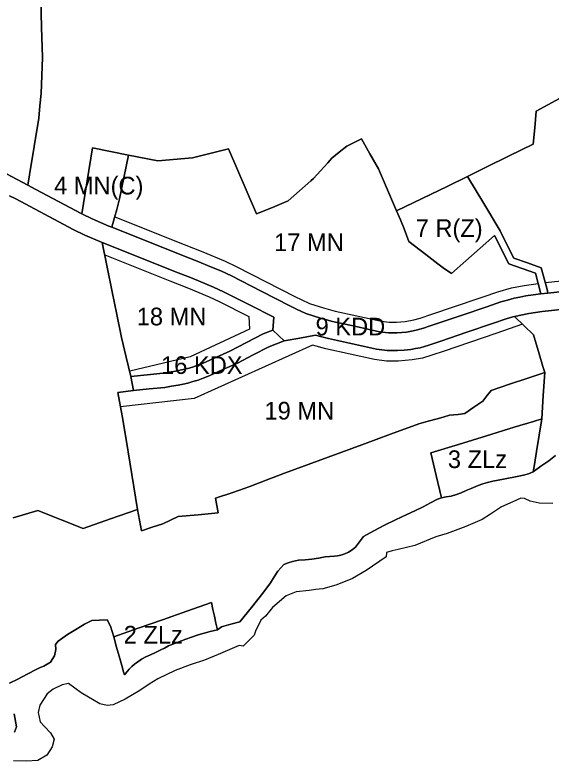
# Model space of a CAD drawing. Extents: x 7423432 to 7425824, y 5537848 to 5539677.
# Drawn here: x 7425103.3 to 7425406.3, y 5538196.8 to 5538618.6 of the extents above; entities that cross this region are included whole.
import ezdxf

# ---------------------------------------------------------------- set-up
doc = ezdxf.new("R2010")
doc.units = 0
for name, color, linetype in [('linie_rozgraniczajace', 7, 'Continuous'), ('linie_zabudowy_nieprzekraczalne', 7, 'Continuous'), ('oznaczenia_przeznaczen', 7, 'Continuous')]:
    doc.layers.add(name, color=color, linetype=linetype)

msp = doc.modelspace()

# ---------------------------------------------------------------- linework, layer by layer
at = {"layer": 'linie_rozgraniczajace'}
for points in [[(7425117.96, 5538627.54), (7425118.36, 5538611.67), (7425118.78, 5538594.47), (7425118.4, 5538584.32), (7425118.02, 5538574.17), (7425117.42, 5538567.24), (7425116.83, 5538560.3), (7425114.2, 5538544.21), (7425111.58, 5538528.12), (7425110.49, 5538522.35), (7425089.18, 5538533.67)], [(7425110.49, 5538522.35), (7425111.58, 5538528.12), (7425114.2, 5538544.21), (7425116.83, 5538560.3), (7425117.42, 5538567.24), (7425118.02, 5538574.17), (7425118.4, 5538584.32), (7425118.78, 5538594.47), (7425118.36, 5538611.67), (7425117.96, 5538627.54)], [(7425502.97, 5538619.64), (7425496.08, 5538615.71), (7425489.2, 5538611.78), (7425484.78, 5538609.38), (7425480.36, 5538606.97), (7425475.97, 5538604.58), (7425471.58, 5538602.19), (7425464.93, 5538599.13), (7425458.27, 5538596.06), (7425453.11, 5538593.1), (7425446.05, 5538589.06), (7425437.25, 5538584.6), (7425428.35, 5538580.1), (7425419.76, 5538575.77), (7425411.17, 5538571.43), (7425404.56, 5538567.83)], [(7425437.03, 5538464.83), (7425404.51, 5538461.39), (7425404.06, 5538463.37), (7425403.03, 5538467.52), (7425400.82, 5538475.69), (7425393.08, 5538478.39), (7425385.35, 5538481.09), (7425381.42, 5538488.84), (7425377.48, 5538496.59), (7425368.31, 5538511.98), (7425359.13, 5538527.36), (7425369.23, 5538532.29), (7425382.73, 5538538.88), (7425396.23, 5538545.46), (7425397.09, 5538554.85), (7425397.96, 5538564.24), (7425404.56, 5538567.83), (7425411.17, 5538571.43)], [(7425404.56, 5538567.83), (7425397.96, 5538564.24), (7425397.09, 5538554.85), (7425396.23, 5538545.46), (7425382.73, 5538538.88), (7425369.23, 5538532.29), (7425359.13, 5538527.36), (7425347.9, 5538521.89), (7425333.43, 5538514.88), (7425318.95, 5538507.87), (7425313.87, 5538519.74), (7425308.78, 5538531.62), (7425303.95, 5538540.04), (7425299.12, 5538548.47), (7425295.01, 5538546.46), (7425290.91, 5538544.46), (7425286.63, 5538541), (7425282.35, 5538537.55), (7425280.08, 5538534.91), (7425276.07, 5538530.52), (7425272.06, 5538526.13), (7425270.57, 5538524.81), (7425264.16, 5538519.15), (7425257.76, 5538513.48), (7425254.17, 5538512), (7425248.84, 5538509.8), (7425239.92, 5538506.11), (7425224.07, 5538542.82), (7425203.67, 5538537.9), (7425184.07, 5538536.07), (7425167.4, 5538539.42), (7425157.3, 5538541.44), (7425147.19, 5538543.47), (7425144.13, 5538524.8), (7425141.08, 5538506.12), (7425140.71, 5538506.31), (7425115.15, 5538519.88), (7425110.49, 5538522.35)], [(7425089.18, 5538533.67), (7425110.49, 5538522.35), (7425115.15, 5538519.88), (7425140.71, 5538506.31), (7425141.08, 5538506.12), (7425146.85, 5538503.3), (7425151.65, 5538501.27), (7425156.44, 5538499.25), (7425158.08, 5538498.59), (7425176.55, 5538491.2), (7425196.66, 5538483.15), (7425207.29, 5538479.07), (7425213.45, 5538476.46), (7425219.61, 5538473.86), (7425225.65, 5538471.04), (7425242.39, 5538462.52), (7425259.14, 5538454), (7425262.36, 5538452.27), (7425267.71, 5538449.9), (7425276.05, 5538447.21), (7425282.88, 5538445.31), (7425296.17, 5538442.42), (7425309.45, 5538439.54), (7425314.41, 5538438.87), (7425319.21, 5538438.85), (7425321.96, 5538439.11), (7425324.71, 5538439.36), (7425327.38, 5538439.85), (7425330.04, 5538440.34), (7425332.1, 5538440.91), (7425334.15, 5538441.47), (7425337.5, 5538442.6), (7425340.85, 5538443.73), (7425355.43, 5538448.66), (7425370, 5538453.59), (7425377.97, 5538456.37), (7425381.68, 5538457.4), (7425385.39, 5538458.43), (7425388.74, 5538459.1), (7425392.08, 5538459.77), (7425396.18, 5538460.36), (7425400.53, 5538460.97), (7425404.51, 5538461.39), (7425437.03, 5538464.83)], [(7425100.17, 5538516.35), (7425103.78, 5538514.59), (7425119.99, 5538505.99), (7425136.2, 5538497.38), (7425142.7, 5538494.19), (7425147.67, 5538492.1), (7425152.64, 5538490), (7425155.48, 5538476.06), (7425158.33, 5538462.13), (7425160.96, 5538449.22), (7425163.6, 5538436.3), (7425166.24, 5538425.22), (7425168.88, 5538414.14), (7425170.26, 5538406.24), (7425161.45, 5538405.16), (7425163.8, 5538391.88), (7425166.16, 5538378.59), (7425169.35, 5538358.82), (7425172.54, 5538339.09), (7425157.24, 5538333.68), (7425141.94, 5538328.32), (7425129.1, 5538333.43), (7425116.26, 5538338.55), (7425102.26, 5538334.37)], [(7425249.55, 5538447.66), (7425235.41, 5538454.86), (7425221.26, 5538462.05), (7425215.55, 5538464.72), (7425203.55, 5538469.79), (7425193.07, 5538473.82), (7425172.85, 5538481.91), (7425152.64, 5538490), (7425147.67, 5538492.1), (7425142.7, 5538494.19), (7425136.2, 5538497.38), (7425119.99, 5538505.99), (7425103.78, 5538514.59), (7425100.17, 5538516.35)], [(7425438.03, 5538454.88), (7425401.39, 5538451), (7425393.77, 5538449.91), (7425385.59, 5538448.11), (7425384.68, 5538447.85), (7425380.96, 5538446.82), (7425373.25, 5538444.13), (7425358.65, 5538439.19), (7425344.05, 5538434.26), (7425340.61, 5538433.09), (7425337.17, 5538431.93), (7425334.74, 5538431.2), (7425332.32, 5538430.47), (7425329.69, 5538429.98), (7425327.07, 5538429.5), (7425323.35, 5538429.17), (7425319.62, 5538428.84), (7425316.66, 5538428.86), (7425313.71, 5538428.87), (7425307.66, 5538429.69), (7425294.07, 5538432.65), (7425280.48, 5538435.6), (7425276.83, 5538436.62), (7425273.17, 5538437.63), (7425264.27, 5538435.96), (7425255.38, 5538434.3), (7425249.01, 5538440.45), (7425249.55, 5538447.66)], [(7425408.89, 5538369.61), (7425405.01, 5538366.49), (7425400.64, 5538363.44), (7425396.26, 5538360.39), (7425396.6, 5538362.43), (7425396.93, 5538364.48), (7425398.11, 5538371.74), (7425399.62, 5538381.03), (7425401.13, 5538390.32), (7425401.95, 5538403.43), (7425402.77, 5538416.53), (7425401.77, 5538419.88), (7425399.62, 5538427.06), (7425396.39, 5538437.82), (7425390.99, 5538442.96), (7425385.59, 5538448.11), (7425393.77, 5538449.91), (7425401.39, 5538451), (7425438.03, 5538454.88)], [(7425382.84, 5538409.81), (7425393.25, 5538413.32), (7425402.77, 5538416.53), (7425401.95, 5538403.43), (7425401.13, 5538390.32), (7425396.35, 5538388.85), (7425385.45, 5538385.49), (7425369.77, 5538380.65), (7425354.08, 5538375.81), (7425338.4, 5538370.97), (7425341.35, 5538358.27), (7425344.31, 5538345.56), (7425342.21, 5538344.95), (7425338.15, 5538342.7), (7425334.09, 5538340.46), (7425329.42, 5538338.3), (7425324.74, 5538336.15), (7425318.44, 5538333.13), (7425312.15, 5538330.1), (7425306.2, 5538326.91), (7425300.26, 5538323.73), (7425298.06, 5538320.71), (7425295.86, 5538317.7), (7425293.89, 5538316.29), (7425291.92, 5538314.89), (7425289.7, 5538314.02), (7425287.48, 5538313.16), (7425285.67, 5538312.86), (7425283.87, 5538312.56), (7425281.25, 5538312.38), (7425278.64, 5538312.19), (7425274.92, 5538311.58), (7425271.19, 5538310.96), (7425267.38, 5538310.66), (7425263.57, 5538310.35), (7425260.09, 5538309.72), (7425257.68, 5538308.87), (7425255.26, 5538308.01), (7425251.84, 5538304.2), (7425249.79, 5538300.93), (7425247.73, 5538297.66), (7425243.47, 5538291.74), (7425236.97, 5538283.62), (7425230.46, 5538275.49), (7425225.24, 5538274.13), (7425220.01, 5538272.77), (7425217.75, 5538271), (7425216.9, 5538274.85), (7425216.05, 5538278.69), (7425215.2, 5538282.53), (7425214.35, 5538286.38), (7425200.53, 5538281.54), (7425186.72, 5538276.7), (7425172.91, 5538271.86), (7425159.1, 5538267.02), (7425157.38, 5538273.1), (7425155.37, 5538276.74), (7425146.79, 5538276.22), (7425142.68, 5538274.14), (7425137.79, 5538271.28), (7425132.91, 5538268.42), (7425130.3, 5538266.53), (7425127.69, 5538264.63), (7425126.25, 5538262.68), (7425126.37, 5538259.9), (7425125.69, 5538256.36), (7425123.38, 5538252.65), (7425121.47, 5538251.6), (7425119.56, 5538250.55), (7425117.49, 5538249.63), (7425115.68, 5538248.83), (7425110.15, 5538245.9), (7425104.89, 5538243.1), (7425100.15, 5538240.76)], [(7425102.26, 5538334.37), (7425116.26, 5538338.55), (7425129.1, 5538333.43), (7425141.94, 5538328.32), (7425157.24, 5538333.68), (7425172.54, 5538339.09), (7425174.78, 5538326.99), (7425180.85, 5538328.99), (7425186.93, 5538330.98), (7425191.22, 5538333), (7425195.51, 5538335.03), (7425206.8, 5538336.06), (7425218.08, 5538337.1), (7425216.63, 5538345.39), (7425226.39, 5538348.72), (7425236.15, 5538352.04), (7425245.37, 5538355.59), (7425255.62, 5538359.55), (7425274.65, 5538366.55), (7425293.67, 5538373.55), (7425299.3, 5538375.63), (7425315.49, 5538381.59), (7425331.67, 5538387.54), (7425336.79, 5538388.93), (7425341.9, 5538390.31), (7425345.39, 5538391.3), (7425348.87, 5538392.29), (7425351.31, 5538392.55), (7425353.76, 5538392.81), (7425357.51, 5538393.35), (7425362.59, 5538396.82), (7425367.68, 5538400.28), (7425370.04, 5538403.29), (7425372.39, 5538406.29), (7425382.84, 5538409.81)], [(7425117.49, 5538249.63), (7425119.56, 5538250.55), (7425121.47, 5538251.6), (7425123.38, 5538252.65), (7425125.69, 5538256.36), (7425126.37, 5538259.9), (7425126.25, 5538262.68), (7425127.69, 5538264.63), (7425130.3, 5538266.53), (7425132.91, 5538268.42), (7425137.79, 5538271.28), (7425142.68, 5538274.14), (7425146.79, 5538276.22), (7425155.37, 5538276.74), (7425157.38, 5538273.1), (7425159.1, 5538267.02), (7425160.75, 5538261.16), (7425162.16, 5538256.18), (7425163.67, 5538250.86), (7425164.7, 5538247.21), (7425165.19, 5538245.47), (7425166.05, 5538246.54), (7425167.81, 5538248.74), (7425169.38, 5538250.19), (7425170.87, 5538251.59), (7425171.92, 5538252.34), (7425174.86, 5538254.42), (7425177.34, 5538255.68), (7425179.82, 5538256.93), (7425182.78, 5538258.27), (7425185.74, 5538259.61), (7425187.84, 5538260.71), (7425190.17, 5538261.95), (7425199.83, 5538265.69), (7425203.01, 5538266.8), (7425206.94, 5538268.17), (7425210.29, 5538269.08), (7425213.64, 5538270), (7425217.75, 5538271), (7425220.01, 5538272.77), (7425225.24, 5538274.13), (7425230.46, 5538275.49), (7425236.97, 5538283.62), (7425243.47, 5538291.74), (7425247.73, 5538297.66), (7425249.79, 5538300.93), (7425251.84, 5538304.2), (7425255.26, 5538308.01), (7425257.68, 5538308.87), (7425260.09, 5538309.72), (7425263.57, 5538310.35), (7425267.38, 5538310.66), (7425271.19, 5538310.96), (7425274.92, 5538311.58), (7425278.64, 5538312.19), (7425281.25, 5538312.38), (7425283.87, 5538312.56), (7425285.67, 5538312.86), (7425287.48, 5538313.16), (7425289.7, 5538314.02), (7425291.92, 5538314.89), (7425293.89, 5538316.29), (7425295.86, 5538317.7), (7425298.06, 5538320.71), (7425300.26, 5538323.73), (7425306.2, 5538326.91), (7425312.15, 5538330.1), (7425318.44, 5538333.13), (7425324.74, 5538336.15), (7425329.42, 5538338.3), (7425334.09, 5538340.46), (7425338.15, 5538342.7), (7425342.21, 5538344.95), (7425344.31, 5538345.56), (7425347.09, 5538346.11), (7425349.87, 5538346.65), (7425352.85, 5538347.58), (7425355.44, 5538348.39), (7425358.3, 5538349.68), (7425361.17, 5538350.97), (7425365.06, 5538352.62), (7425367.78, 5538353.5), (7425370.49, 5538354.37), (7425373.48, 5538355.01), (7425376.47, 5538355.66), (7425379.4, 5538356.21), (7425382.33, 5538356.77), (7425385.27, 5538357.32), (7425388.2, 5538357.87), (7425390.78, 5538358.52), (7425393.55, 5538359.24), (7425396.26, 5538360.39), (7425400.64, 5538363.44), (7425405.01, 5538366.49), (7425408.89, 5538369.61)], [(7425407.26, 5538342.36), (7425399.61, 5538342.57), (7425394.61, 5538343.69), (7425391.28, 5538345.22), (7425389.19, 5538345.4), (7425384.81, 5538343.44), (7425378.34, 5538340.46), (7425372.12, 5538336.44), (7425367.41, 5538333.38), (7425358.24, 5538329.36), (7425347.54, 5538325.5), (7425341.13, 5538323.66), (7425329.27, 5538318.62), (7425319.87, 5538316.49), (7425316.55, 5538315.74), (7425313.28, 5538314.69), (7425313.2, 5538312.29), (7425301.73, 5538304.56), (7425294.03, 5538300.09), (7425288.97, 5538297.97), (7425284.63, 5538296.17), (7425277.3, 5538294.27), (7425273.09, 5538293.72), (7425269.51, 5538293.19), (7425262.34, 5538292.56), (7425256.67, 5538290.14), (7425248.95, 5538283.67), (7425244.83, 5538278.72), (7425242.33, 5538276.53), (7425239.28, 5538270.16), (7425238.53, 5538268.08), (7425232.22, 5538261.74), (7425230.01, 5538262.2), (7425218.12, 5538257.07), (7425210.46, 5538253.89), (7425202.24, 5538251.13), (7425193.89, 5538247.94), (7425184.05, 5538243.3), (7425179.12, 5538240.24), (7425173.87, 5538236.71), (7425165.65, 5538231.75), (7425158.87, 5538228.68), (7425155.36, 5538228.15), (7425151.19, 5538229.26), (7425140.71, 5538235.43), (7425133.48, 5538240.71), (7425129.89, 5538239.94), (7425124.87, 5538237.43), (7425121.43, 5538234.81), (7425117.31, 5538228.46), (7425116.37, 5538224.36), (7425117.48, 5538219), (7425119.93, 5538216.34), (7425123.37, 5538212.73), (7425125.42, 5538209.19), (7425124.4, 5538204.88), (7425121.35, 5538200.07), (7425116.28, 5538197.15), (7425109.59, 5538196.81), (7425102.38, 5538196.97)], [(7425100.15, 5538240.76), (7425104.89, 5538243.1), (7425110.15, 5538245.9), (7425115.68, 5538248.83), (7425117.49, 5538249.63)], [(7425102.8, 5538223.48), (7425104.19, 5538216.25), (7425103.12, 5538213.21)], [(7425103.12, 5538213.21), (7425104.19, 5538216.25), (7425102.8, 5538223.48)]]:
    msp.add_lwpolyline(points, dxfattribs=at)
for points in [[(7425158.08, 5538498.59), (7425159.55, 5538504.03), (7425160.81, 5538508.65), (7425162.44, 5538514.65), (7425167.4, 5538539.42), (7425184.07, 5538536.07), (7425203.67, 5538537.9), (7425224.07, 5538542.82), (7425239.92, 5538506.11), (7425248.84, 5538509.8), (7425254.17, 5538512), (7425257.76, 5538513.48), (7425264.16, 5538519.15), (7425270.57, 5538524.81), (7425272.06, 5538526.13), (7425276.07, 5538530.52), (7425280.08, 5538534.91), (7425282.35, 5538537.55), (7425286.63, 5538541), (7425290.91, 5538544.46), (7425295.01, 5538546.46), (7425299.12, 5538548.47), (7425303.95, 5538540.04), (7425308.78, 5538531.62), (7425313.87, 5538519.74), (7425318.95, 5538507.87), (7425321.15, 5538502.74), (7425323.35, 5538497.61), (7425325.98, 5538490.61), (7425335.63, 5538483.14), (7425342.28, 5538477.99), (7425345.29, 5538475.66), (7425350, 5538472.47), (7425374.38, 5538493.86), (7425382.51, 5538477.85), (7425397.51, 5538472.61), (7425400.53, 5538460.97), (7425396.18, 5538460.36), (7425392.08, 5538459.77), (7425388.74, 5538459.1), (7425385.39, 5538458.43), (7425381.68, 5538457.4), (7425377.97, 5538456.37), (7425370, 5538453.59), (7425355.43, 5538448.66), (7425340.85, 5538443.73), (7425337.5, 5538442.6), (7425334.15, 5538441.47), (7425332.1, 5538440.91), (7425330.04, 5538440.34), (7425327.38, 5538439.85), (7425324.71, 5538439.36), (7425321.96, 5538439.11), (7425319.21, 5538438.85), (7425314.41, 5538438.87), (7425309.45, 5538439.54), (7425296.17, 5538442.42), (7425282.88, 5538445.31), (7425276.05, 5538447.21), (7425267.71, 5538449.9), (7425262.36, 5538452.27), (7425259.14, 5538454), (7425242.39, 5538462.52), (7425225.65, 5538471.04), (7425219.61, 5538473.86), (7425213.45, 5538476.46), (7425207.29, 5538479.07), (7425196.66, 5538483.15), (7425176.55, 5538491.2)], [(7425141.08, 5538506.12), (7425144.13, 5538524.8), (7425147.19, 5538543.47), (7425157.3, 5538541.44), (7425167.4, 5538539.42), (7425162.44, 5538514.65), (7425160.81, 5538508.65), (7425159.55, 5538504.03), (7425158.08, 5538498.59), (7425156.44, 5538499.25), (7425151.65, 5538501.27), (7425146.85, 5538503.3)], [(7425318.95, 5538507.87), (7425333.43, 5538514.88), (7425347.9, 5538521.89), (7425359.13, 5538527.36), (7425368.31, 5538511.98), (7425377.48, 5538496.59), (7425381.42, 5538488.84), (7425385.35, 5538481.09), (7425393.08, 5538478.39), (7425400.82, 5538475.69), (7425403.03, 5538467.52), (7425404.06, 5538463.37), (7425404.51, 5538461.39), (7425400.53, 5538460.97), (7425397.51, 5538472.61), (7425382.51, 5538477.85), (7425374.38, 5538493.86), (7425350, 5538472.47), (7425345.29, 5538475.66), (7425342.28, 5538477.99), (7425335.63, 5538483.14), (7425325.98, 5538490.61), (7425323.35, 5538497.61), (7425321.15, 5538502.74)], [(7425152.64, 5538490), (7425172.85, 5538481.91), (7425193.07, 5538473.82), (7425203.55, 5538469.79), (7425215.55, 5538464.72), (7425221.26, 5538462.05), (7425235.41, 5538454.86), (7425249.55, 5538447.66), (7425249.01, 5538440.45), (7425243.56, 5538438.39), (7425234.13, 5538433.49), (7425224.71, 5538428.58), (7425217.16, 5538425.17), (7425209.6, 5538421.76), (7425206.94, 5538420.73), (7425204.28, 5538419.7), (7425201.7, 5538418.99), (7425199.12, 5538418.27), (7425194.06, 5538417.2), (7425190.54, 5538416.61), (7425187.02, 5538416.01), (7425177.95, 5538415.08), (7425168.88, 5538414.14), (7425166.24, 5538425.22), (7425163.6, 5538436.3), (7425160.96, 5538449.22), (7425158.33, 5538462.13), (7425155.48, 5538476.06)], [(7425161.45, 5538405.16), (7425170.26, 5538406.24), (7425179.18, 5538407.16), (7425188.1, 5538408.08), (7425191.83, 5538408.71), (7425195.55, 5538409.34), (7425198.29, 5538409.92), (7425201.02, 5538410.5), (7425203.91, 5538411.3), (7425206.8, 5538412.1), (7425209.75, 5538413.24), (7425213.13, 5538414.57), (7425220.87, 5538418.1), (7425229.06, 5538421.83), (7425237.94, 5538426.45), (7425246.83, 5538431.07), (7425251.1, 5538432.69), (7425255.38, 5538434.3), (7425264.27, 5538435.96), (7425273.17, 5538437.63), (7425276.83, 5538436.62), (7425280.48, 5538435.6), (7425294.07, 5538432.65), (7425307.66, 5538429.69), (7425313.71, 5538428.87), (7425316.66, 5538428.86), (7425319.62, 5538428.84), (7425323.35, 5538429.17), (7425327.07, 5538429.5), (7425329.69, 5538429.98), (7425332.32, 5538430.47), (7425334.74, 5538431.2), (7425337.17, 5538431.93), (7425340.61, 5538433.09), (7425344.05, 5538434.26), (7425358.65, 5538439.19), (7425373.25, 5538444.13), (7425380.96, 5538446.82), (7425384.68, 5538447.85), (7425385.59, 5538448.11), (7425390.99, 5538442.96), (7425396.39, 5538437.82), (7425399.62, 5538427.06), (7425401.77, 5538419.88), (7425402.77, 5538416.53), (7425393.25, 5538413.32), (7425382.84, 5538409.81), (7425372.39, 5538406.29), (7425370.04, 5538403.29), (7425367.68, 5538400.28), (7425362.59, 5538396.82), (7425357.51, 5538393.35), (7425353.76, 5538392.81), (7425351.31, 5538392.55), (7425348.87, 5538392.29), (7425345.39, 5538391.3), (7425341.9, 5538390.31), (7425336.79, 5538388.93), (7425331.67, 5538387.54), (7425315.49, 5538381.59), (7425299.3, 5538375.63), (7425293.67, 5538373.55), (7425274.65, 5538366.55), (7425255.62, 5538359.55), (7425245.37, 5538355.59), (7425236.15, 5538352.04), (7425226.39, 5538348.72), (7425216.63, 5538345.39), (7425218.08, 5538337.1), (7425206.8, 5538336.06), (7425195.51, 5538335.03), (7425191.22, 5538333), (7425186.93, 5538330.98), (7425180.85, 5538328.99), (7425174.78, 5538326.99), (7425172.54, 5538339.09), (7425169.35, 5538358.82), (7425166.16, 5538378.59), (7425163.8, 5538391.88)], [(7425168.88, 5538414.14), (7425177.95, 5538415.08), (7425187.02, 5538416.01), (7425190.54, 5538416.61), (7425194.06, 5538417.2), (7425199.12, 5538418.27), (7425201.7, 5538418.99), (7425204.28, 5538419.7), (7425206.94, 5538420.73), (7425209.6, 5538421.76), (7425217.16, 5538425.17), (7425224.71, 5538428.58), (7425234.13, 5538433.49), (7425243.56, 5538438.39), (7425249.01, 5538440.45), (7425255.38, 5538434.3), (7425251.1, 5538432.69), (7425246.83, 5538431.07), (7425237.94, 5538426.45), (7425229.06, 5538421.83), (7425220.87, 5538418.1), (7425213.13, 5538414.57), (7425209.75, 5538413.24), (7425206.8, 5538412.1), (7425203.91, 5538411.3), (7425201.02, 5538410.5), (7425198.29, 5538409.92), (7425195.55, 5538409.34), (7425191.83, 5538408.71), (7425188.1, 5538408.08), (7425179.18, 5538407.16), (7425170.26, 5538406.24)], [(7425338.4, 5538370.97), (7425354.08, 5538375.81), (7425369.77, 5538380.65), (7425385.45, 5538385.49), (7425396.35, 5538388.85), (7425401.13, 5538390.32), (7425399.62, 5538381.03), (7425398.11, 5538371.74), (7425396.93, 5538364.48), (7425396.6, 5538362.43), (7425396.26, 5538360.39), (7425393.55, 5538359.24), (7425390.78, 5538358.52), (7425388.2, 5538357.87), (7425385.27, 5538357.32), (7425382.33, 5538356.77), (7425379.4, 5538356.21), (7425376.47, 5538355.66), (7425373.48, 5538355.01), (7425370.49, 5538354.37), (7425367.78, 5538353.5), (7425365.06, 5538352.62), (7425361.17, 5538350.97), (7425358.3, 5538349.68), (7425355.44, 5538348.39), (7425352.85, 5538347.58), (7425349.87, 5538346.65), (7425347.09, 5538346.11), (7425344.31, 5538345.56), (7425341.35, 5538358.27)], [(7425159.1, 5538267.02), (7425172.91, 5538271.86), (7425186.72, 5538276.7), (7425200.53, 5538281.54), (7425214.35, 5538286.38), (7425215.2, 5538282.53), (7425216.05, 5538278.69), (7425216.9, 5538274.85), (7425217.75, 5538271), (7425213.64, 5538270), (7425210.29, 5538269.08), (7425206.94, 5538268.17), (7425203.01, 5538266.8), (7425199.83, 5538265.69), (7425190.17, 5538261.95), (7425187.84, 5538260.71), (7425185.74, 5538259.61), (7425182.78, 5538258.27), (7425179.82, 5538256.93), (7425177.34, 5538255.68), (7425174.86, 5538254.42), (7425171.92, 5538252.34), (7425170.87, 5538251.59), (7425169.38, 5538250.19), (7425167.81, 5538248.74), (7425166.05, 5538246.54), (7425165.19, 5538245.47), (7425164.7, 5538247.21), (7425163.67, 5538250.86), (7425162.16, 5538256.18), (7425160.75, 5538261.16)]]:
    msp.add_lwpolyline(points, close=True, dxfattribs=at)
at = {"layer": 'linie_zabudowy_nieprzekraczalne'}
for points in [[(7425403.1, 5538467.28), (7425472.86, 5538474.66), (7425481.7, 5538475.74), (7425635.24, 5538496.85), (7425636.24, 5538494.22), (7425636.24, 5538494.22), (7425672.06, 5538507.66), (7425659.74, 5538532.64), (7425653.28, 5538544.99), (7425648.13, 5538557.43), (7425639.35, 5538584.86), (7425631.55, 5538609.21), (7425625.04, 5538629.34), (7425617.08, 5538652.83), (7425612.13, 5538667.84), (7425599.82, 5538705.08), (7425596.78, 5538715.41), (7425584.84, 5538771.82), (7425577.47, 5538810.31), (7425570.88, 5538837.86)], [(7425159.66, 5538504.42), (7425198.85, 5538488.74), (7425209.53, 5538484.63), (7425222.05, 5538479.35), (7425228.28, 5538476.43), (7425261.91, 5538459.32), (7425265, 5538457.67), (7425269.85, 5538455.51), (7425277.77, 5538452.96), (7425284.33, 5538451.14), (7425310.49, 5538445.45), (7425314.83, 5538444.87), (7425318.94, 5538444.85), (7425323.88, 5538445.31), (7425328.7, 5538446.2), (7425332.4, 5538447.21), (7425338.93, 5538449.42), (7425365.2, 5538458.3)], [(7425154.07, 5538482.96), (7425190.88, 5538468.24), (7425201.3, 5538464.23), (7425213.11, 5538459.24), (7425218.63, 5538456.66), (7425235.57, 5538448.04), (7425235.84, 5538440.93), (7425202.39, 5538425.4), (7425202.39, 5538425.4), (7425202.39, 5538425.4), (7425202.39, 5538425.4), (7425202.39, 5538425.4), (7425168.14, 5538417.24)], [(7425365.2, 5538458.3), (7425368.05, 5538459.26), (7425376.18, 5538462.1), (7425384, 5538464.27), (7425391.07, 5538465.68), (7425399.01, 5538466.82)], [(7425390.22, 5538443.7), (7425375.2, 5538438.45), (7425345.97, 5538428.58), (7425338.99, 5538426.21), (7425333.73, 5538424.63), (7425327.88, 5538423.54), (7425319.87, 5538422.84), (7425313.29, 5538422.87), (7425306.62, 5538423.78), (7425279.04, 5538429.77), (7425271.52, 5538431.86), (7425204.54, 5538401.8), (7425162.88, 5538397.11)]]:
    msp.add_lwpolyline(points, dxfattribs=at)

# ---------------------------------------------------------------- texts
at = {"layer": 'oznaczenia_przeznaczen'}
for s, p in [('4 MN(C)', (7425125.41, 5538517.12)), ('7 R(Z)', (7425329.79, 5538493.1)), ('17 MN', (7425249.77, 5538485.06)), ('18 MN', (7425172.13, 5538443.11)), ('9 KDD', (7425273.22, 5538437.42)), ('16 KDX', (7425185.87, 5538415.65)), ('19 MN', (7425244.34, 5538389.88)), ('3 ZLz', (7425348, 5538362.44)), ('2 ZLz', (7425164.79, 5538263.26))]:
    msp.add_text(s, height=10, dxfattribs=at).set_placement(p)

doc.saveas('drawing.dxf')
